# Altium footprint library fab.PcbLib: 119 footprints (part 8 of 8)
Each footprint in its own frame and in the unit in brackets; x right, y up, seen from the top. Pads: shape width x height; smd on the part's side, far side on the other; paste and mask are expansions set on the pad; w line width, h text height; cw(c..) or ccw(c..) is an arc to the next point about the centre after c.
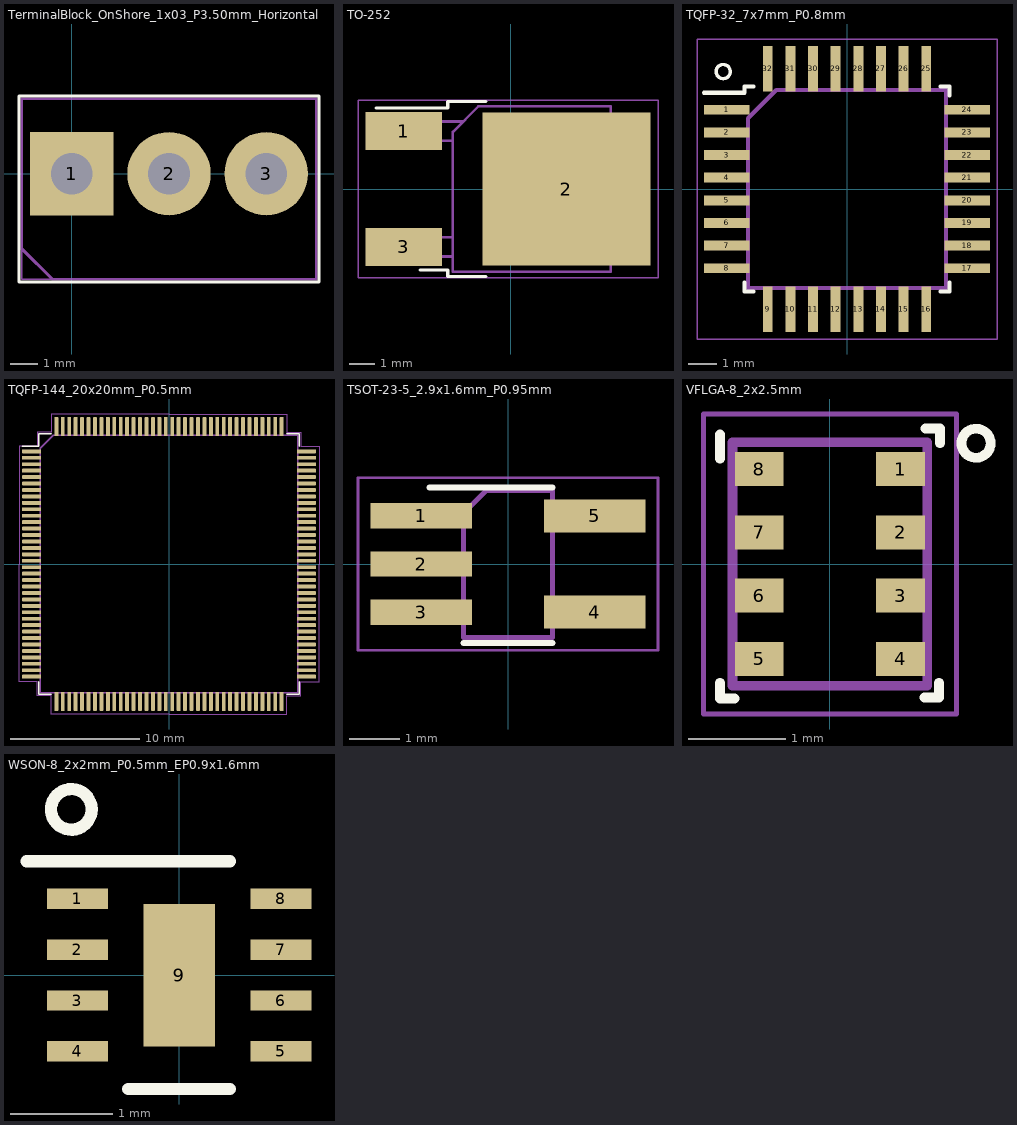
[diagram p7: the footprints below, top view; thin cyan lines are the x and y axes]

## TerminalBlock_OnShore_1x03_P3.50mm_Horizontal [mm]
pads (3):
  rect 3x3 hole 1.5: 1(0,0)
  round 3 hole 1.5: 2(3.5,0) 3(7,0)
F.SilkS:
  lines w0.12: -1.9,-3.9 -1.9,2.8 8.9,2.8 8.9,-3.9 -1.9,-3.9
F.CrtYd:
  lines w0.05: -1.8,-3.8 8.8,-3.8 8.8,2.7 -1.8,2.7 -1.8,-3.8
F.Fab:
  lines w0.1: -1.8,-2.7 -1.8,2.7 8.8,2.7 8.8,-3.8 -0.7,-3.8 -1.8,-2.7
  text "%R" at 3.107,-3.194 h1

## TO-252 [mm]
pads (3):
  rect 3x1.5 smd: 1(-4.2,2.28) 3(-4.2,-2.28)
  rect 6.6x6 smd: 2(2.2,0)
F.SilkS:
  lines w0.12: -5.3,3.18 -2.47,3.18 -2.47,3.45 -0.97,3.45 ; -3.57,-3.18 -2.47,-3.18 -2.47,-3.45 -0.97,-3.45
F.CrtYd:
  lines w0.05: -6,-3.5 5.8,-3.5 5.8,3.5 -6,3.5 -6,-3.5
F.Fab:
  lines w0.1: -2.27,-2.655 -4.97,-2.655 -4.97,-1.905 -2.27,-1.905 ; -2.27,1.905 -4.97,1.905 -4.97,2.655 -1.865,2.655 ; 3.95,-2.7 4.95,-2.7 ; 3.95,2.7 4.95,2.7 ; -2.27,-3.25 -2.27,2.25 -1.27,3.25 3.95,3.25 3.95,-3.25 -2.27,-3.25
  text "%R" at -0.393,-0.294 h1

## TQFP-32_7x7mm_P0.8mm [mm]
pads (32):
  rect 1.6x0.35 smd: 1(-4.25,2.8) 2(-4.25,2) 3(-4.25,1.2) 4(-4.25,0.4) 5(-4.25,-0.4) 6(-4.25,-1.2) 7(-4.25,-2) 8(-4.25,-2.8) 17(4.25,-2.8) 18(4.25,-2) 19(4.25,-1.2) 20(4.25,-0.4) 21(4.25,0.4) 22(4.25,1.2) 23(4.25,2) 24(4.25,2.8)
  rect 0.35x1.6 smd: 9(-2.8,-4.25) 10(-2,-4.25) 11(-1.2,-4.25) 12(-0.4,-4.25) 13(0.4,-4.25) 14(1.2,-4.25) 15(2,-4.25) 16(2.8,-4.25) 25(2.8,4.25) 26(2,4.25) 27(1.2,4.25) 28(0.4,4.25) 29(-0.4,4.25) 30(-1.2,4.25) 31(-2,4.25) 32(-2.8,4.25)
F.SilkS:
  circle w0.12: c-4.375,4.15 r0.25
  lines w0.15: -5.05,3.4 -3.625,3.4 -3.625,3.625 -3.3,3.625 ; -3.625,-3.3 -3.625,-3.625 -3.3,-3.625 ; 3.3,-3.625 3.625,-3.625 3.625,-3.3 ; 3.3,3.625 3.625,3.625 3.625,3.3
F.CrtYd:
  lines w0.05: -5.3,-5.3 5.3,-5.3 5.3,5.3 -5.3,5.3 -5.3,-5.3
F.Fab:
  lines w0.15: -3.5,-3.5 -3.5,2.5 -2.5,3.5 3.5,3.5 3.5,-3.5 -3.5,-3.5
  text "%R" at -0.393,-0.294 h1

## TQFP-144_20x20mm_P0.5mm [mm]
pads (144):
  rrect25% 1.475x0.3 smd: 1(-10.663,8.75) 2(-10.663,8.25) 3(-10.663,7.75) 4(-10.663,7.25) 5(-10.663,6.75) 6(-10.663,6.25) 7(-10.663,5.75) 8(-10.663,5.25) 9(-10.663,4.75) 10(-10.663,4.25) 11(-10.663,3.75) 12(-10.663,3.25) 13(-10.663,2.75) 14(-10.663,2.25) 15(-10.663,1.75) 16(-10.663,1.25) 17(-10.663,0.75) 18(-10.663,0.25) 19(-10.663,-0.25) 20(-10.663,-0.75) 21(-10.663,-1.25) 22(-10.663,-1.75) 23(-10.663,-2.25) 24(-10.663,-2.75) 25(-10.663,-3.25) 26(-10.663,-3.75) 27(-10.663,-4.25) 28(-10.663,-4.75) 29(-10.663,-5.25) 30(-10.663,-5.75) 31(-10.663,-6.25) 32(-10.663,-6.75) 33(-10.663,-7.25) 34(-10.663,-7.75) 35(-10.663,-8.25) 36(-10.663,-8.75) 73(10.663,-8.75) 74(10.663,-8.25) 75(10.663,-7.75) 76(10.663,-7.25) 77(10.663,-6.75) 78(10.663,-6.25) 79(10.663,-5.75) 80(10.663,-5.25) 81(10.663,-4.75) 82(10.663,-4.25) 83(10.663,-3.75) 84(10.663,-3.25) 85(10.663,-2.75) 86(10.663,-2.25) 87(10.663,-1.75) 88(10.663,-1.25) 89(10.663,-0.75) 90(10.663,-0.25) 91(10.663,0.25) 92(10.663,0.75) 93(10.663,1.25) 94(10.663,1.75) 95(10.663,2.25) 96(10.663,2.75) 97(10.663,3.25) 98(10.663,3.75) 99(10.663,4.25) 100(10.663,4.75) 101(10.663,5.25) 102(10.663,5.75) 103(10.663,6.25) 104(10.663,6.75) 105(10.663,7.25) 106(10.663,7.75) 107(10.663,8.25) 108(10.663,8.75)
  rrect25% 0.3x1.475 smd: 37(-8.75,-10.663) 38(-8.25,-10.663) 39(-7.75,-10.663) 40(-7.25,-10.663) 41(-6.75,-10.663) 42(-6.25,-10.663) 43(-5.75,-10.663) 44(-5.25,-10.663) 45(-4.75,-10.663) 46(-4.25,-10.663) 47(-3.75,-10.663) 48(-3.25,-10.663) 49(-2.75,-10.663) 50(-2.25,-10.663) 51(-1.75,-10.663) 52(-1.25,-10.663) 53(-0.75,-10.663) 54(-0.25,-10.663) 55(0.25,-10.663) 56(0.75,-10.663) 57(1.25,-10.663) 58(1.75,-10.663) 59(2.25,-10.663) 60(2.75,-10.663) 61(3.25,-10.663) 62(3.75,-10.663) 63(4.25,-10.663) 64(4.75,-10.663) 65(5.25,-10.663) 66(5.75,-10.663) 67(6.25,-10.663) 68(6.75,-10.663) 69(7.25,-10.663) 70(7.75,-10.663) 71(8.25,-10.663) 72(8.75,-10.663) 109(8.75,10.663) 110(8.25,10.663) 111(7.75,10.663) 112(7.25,10.663) 113(6.75,10.663) 114(6.25,10.663) 115(5.75,10.663) 116(5.25,10.663) 117(4.75,10.663) 118(4.25,10.663) 119(3.75,10.663) 120(3.25,10.663) 121(2.75,10.663) 122(2.25,10.663) 123(1.75,10.663) 124(1.25,10.663) 125(0.75,10.663) 126(0.25,10.663) 127(-0.25,10.663) 128(-0.75,10.663) 129(-1.25,10.663) 130(-1.75,10.663) 131(-2.25,10.663) 132(-2.75,10.663) 133(-3.25,10.663) 134(-3.75,10.663) 135(-4.25,10.663) 136(-4.75,10.663) 137(-5.25,10.663) 138(-5.75,10.663) 139(-6.25,10.663) 140(-6.75,10.663) 141(-7.25,10.663) 142(-7.75,10.663) 143(-8.25,10.663) 144(-8.75,10.663)
F.SilkS:
  lines w0.12: -11.4,9.16 -10.11,9.16 -10.11,10.11 -9.16,10.11 ; -10.11,-9.16 -10.11,-10.11 -9.16,-10.11 ; 9.16,-10.11 10.11,-10.11 10.11,-9.16 ; 9.16,10.11 10.11,10.11 10.11,9.16
F.CrtYd:
  lines w0.05: -11.65,-9.15 -11.65,0 -11.65,9.15 -10.25,9.15 -10.25,10.25 -9.15,10.25 -9.15,11.65 0,11.65 9.15,11.65 9.15,10.25 10.25,10.25 10.25,9.15 11.65,9.15 11.65,0 11.65,-9.15 10.25,-9.15 10.25,-10.25 9.15,-10.25 9.15,-11.65 0,-11.65 -9.15,-11.65 -9.15,-10.25 -10.25,-10.25 -10.25,-9.15 -11.65,-9.15
F.Fab:
  lines w0.1: -10,-10 -10,9 -9,10 10,10 10,-10 -10,-10
  text "%R" at -0.393,-0.294 h1

## TSOT-23-5_2.9x1.6mm_P0.95mm [mm]
pads (5):
  rect 2x0.5 smd: 1(-1.71,0.95) 2(-1.71,0) 3(-1.71,-0.95)
  rect 2x0.65 smd: 4(1.71,-0.95) 5(1.71,0.95)
F.SilkS:
  lines w0.12: -1.55,1.51 0.88,1.51 ; -0.88,-1.56 0.88,-1.56
F.CrtYd:
  lines w0.05: -2.96,-1.7 2.96,-1.7 2.96,1.7 -2.96,1.7 -2.96,-1.7
F.Fab:
  lines w0.1: -0.88,-1.45 0.88,-1.45 0.88,1.45 -0.43,1.45 -0.88,1 -0.88,-1.45
  text "%R" at 0.147,-0.197 h0.5

## VFLGA-8_2x2.5mm [mm]
pads (8):
  rect 0.5x0.35 smd: 1(0.725,0.975) 2(0.725,0.325) 3(0.725,-0.325) 4(0.725,-0.975) 5(-0.725,-0.975) 6(-0.725,-0.325) 7(-0.725,0.325) 8(-0.725,0.975)
F.SilkS:
  circle w0.1: c1.5,1.24 r0.15
  lines w0.1: -1.13,-1.38 -0.98,-1.38 ; -1.13,-1.37 -1.13,-1.22 ; -1.13,1.08 -1.13,1.33 ; 0.97,-1.37 1.12,-1.37 1.12,-1.22 ; 0.98,1.39 1.13,1.39 1.13,1.24
F.CrtYd:
  lines w0.05: -1.3,-1.54 1.3,-1.54 1.3,1.54 -1.3,1.54 -1.3,-1.54
F.Fab:
  lines w0.1: -1,-1.25 1,-1.25 1,1.25 -1,1.25 -1,-1.25
  text "%R" at -0.197,-0.147 h0.5

## WSON-8_2x2mm_P0.5mm_EP0.9x1.6mm [mm]
pads (9):
  rect 0.6x0.2 smd: 1(-1,0.75) 2(-1,0.25) 3(-1,-0.25) 4(-1,-0.75) 5(1,-0.75) 6(1,-0.25) 7(1,0.25) 8(1,0.75)
  rect 0.7x1.4 smd: 9(0,0)
F.SilkS:
  circle w0.12: c-1.06,1.63 r0.2
  lines w0.12: -1.5,1.12 0.5,1.12 ; -0.5,-1.12 0.5,-1.12
F.Fab:
  text "%R" at -0.275,-0.205 h0.7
